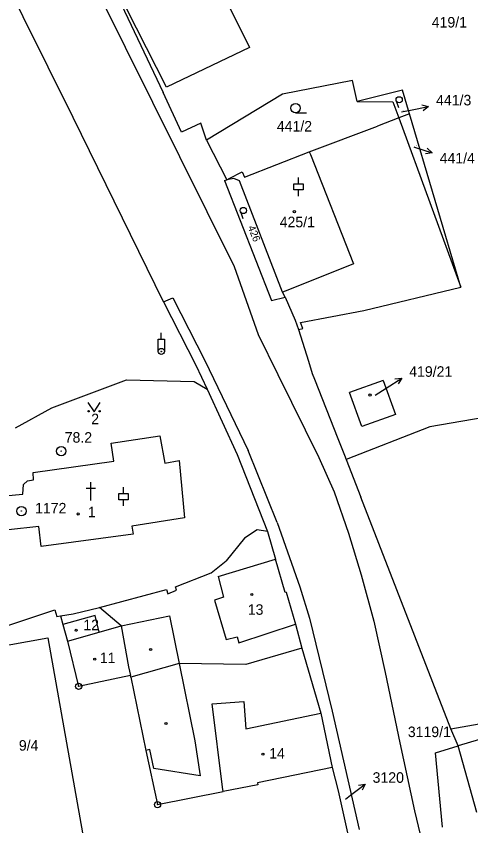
# Model space of a CAD drawing. Extents: x -736345 to -729997, y -1130177 to -1122501.
# Drawn here: x -733626.2 to -733552.8, y -1126891.5 to -1126760.8 of the extents above; entities that cross this region are included whole.
import ezdxf

# ---------------------------------------------------------------- set-up
doc = ezdxf.new("R2010")
doc.units = 0
for name, color, linetype in [('Vrstva 1', 7, 'Continuous'), ('Vrstva 16', 7, 'Continuous'), ('Vrstva 17', 7, 'Continuous'), ('Vrstva 18', 7, 'Continuous'), ('Vrstva 19', 7, 'Continuous'), ('Vrstva 25', 7, 'Continuous'), ('Vrstva 4', 7, 'Continuous')]:
    doc.layers.add(name, color=color, linetype=linetype)

msp = doc.modelspace()

# ---------------------------------------------------------------- linework, layer by layer
at = {"layer": 'Vrstva 1'}
for points in [[(-733617, -1126777.14), (-733653.37, -1126703.96)], [(-733630.68, -1126721.44), (-733590.98, -1126801.18)], [(-733600.44, -1126741.82), (-733588.52, -1126765.83)], [(-733601.94, -1126772.22), (-733616.47, -1126743.62)], [(-733616.47, -1126743.62), (-733602.44, -1126773.11)], [(-733588.52, -1126765.83), (-733601.94, -1126772.22)], [(-733571.88, -1126771.14), (-733583.17, -1126773.36)], [(-733571.13, -1126774.55), (-733571.88, -1126771.14)], [(-733599.49, -1126779.5), (-733602.44, -1126773.11)], [(-733563.83, -1126772.7), (-733571.13, -1126774.55)], [(-733562.69, -1126776.53), (-733563.83, -1126772.7)], [(-733583.17, -1126773.36), (-733595.44, -1126780.77)], [(-733571.13, -1126774.55), (-733565.34, -1126774.59)], [(-733565.34, -1126774.59), (-733564.39, -1126777.18)], [(-733562.69, -1126776.53), (-733564.39, -1126777.18)], [(-733554.36, -1126804.53), (-733562.69, -1126776.53)], [(-733602.39, -1126806.9), (-733617, -1126777.14)], [(-733596.4, -1126778.03), (-733599.49, -1126779.5)], [(-733595.44, -1126780.77), (-733596.4, -1126778.03)], [(-733564.39, -1126777.18), (-733567.85, -1126778.51)], [(-733564.39, -1126777.18), (-733554.36, -1126804.53)], [(-733578.86, -1126782.68), (-733567.85, -1126778.51)], [(-733595.44, -1126780.77), (-733592.18, -1126787.18)], [(-733589.3, -1126786.74), (-733578.86, -1126782.68)], [(-733591.79, -1126786.98), (-733589.68, -1126785.92)], [(-733589.68, -1126785.92), (-733589.3, -1126786.74)], [(-733592.56, -1126787.31), (-733592.18, -1126787.18)], [(-733592.56, -1126787.31), (-733584.96, -1126806.68)], [(-733592.18, -1126787.18), (-733591.79, -1126786.98)], [(-733591.07, -1126787), (-733592.18, -1126787.18)], [(-733590.15, -1126787.35), (-733591.07, -1126787)], [(-733583.16, -1126805.33), (-733590.15, -1126787.35)], [(-733590.98, -1126801.18), (-733587.1, -1126812.15)], [(-733570.07, -1126808.28), (-733554.36, -1126804.53)], [(-733582.75, -1126806.11), (-733583.16, -1126805.33)], [(-733602.39, -1126806.9), (-733600.91, -1126806.24)], [(-733602.39, -1126806.9), (-733597.18, -1126817.11)], [(-733600.91, -1126806.24), (-733595.71, -1126816.37)], [(-733584.96, -1126806.68), (-733582.75, -1126806.11)], [(-733582.75, -1126806.11), (-733581.16, -1126809.87)], [(-733580.27, -1126810.23), (-733570.07, -1126808.28)], [(-733581.16, -1126809.87), (-733580.58, -1126811.37)], [(-733579.89, -1126811.2), (-733580.27, -1126810.23)], [(-733587.1, -1126812.15), (-733583.93, -1126818.6)], [(-733580.58, -1126811.37), (-733579.89, -1126811.2)], [(-733580.58, -1126811.37), (-733578.99, -1126816.49)], [(-733597.18, -1126817.11), (-733595.38, -1126821.01)], [(-733595.71, -1126816.37), (-733588.71, -1126830.89)], [(-733578.99, -1126816.49), (-733578.38, -1126818.45)], [(-733583.93, -1126818.6), (-733577.33, -1126832)], [(-733578.38, -1126818.45), (-733578.01, -1126819.38)], [(-733620.45, -1126824), (-733608.4, -1126819.5)], [(-733608.4, -1126819.5), (-733597.45, -1126819.75)], [(-733597.45, -1126819.75), (-733595.38, -1126821.01)], [(-733578.01, -1126819.38), (-733574.24, -1126828.95)], [(-733566.92, -1126819.58), (-733572.34, -1126821.53)], [(-733566.92, -1126819.58), (-733564.94, -1126825.06)], [(-733595.38, -1126821.01), (-733590.52, -1126831.56)], [(-733570.36, -1126827.02), (-733572.34, -1126821.53)], [(-733626.3, -1126827.23), (-733620.45, -1126824)], [(-733564.94, -1126825.06), (-733570.36, -1126827.02)], [(-733543.7, -1126824.36), (-733559.37, -1126827.08)], [(-733559.37, -1126827.08), (-733572.91, -1126832.34)], [(-733610.88, -1126829.73), (-733603, -1126828.54)], [(-733603, -1126828.54), (-733602.19, -1126832.92)], [(-733574.24, -1126828.95), (-733573.18, -1126831.64)], [(-733610.45, -1126832.62), (-733610.88, -1126829.73)], [(-733590.52, -1126831.56), (-733585.62, -1126843.98)], [(-733584.04, -1126842.52), (-733588.71, -1126830.89)], [(-733577.33, -1126832), (-733574.86, -1126837.58)], [(-733573.18, -1126831.64), (-733572.91, -1126832.34)], [(-733623.46, -1126834.42), (-733610.45, -1126832.62)], [(-733602.19, -1126832.92), (-733599.9, -1126832.5)], [(-733599.9, -1126832.5), (-733599, -1126841.74)], [(-733572.91, -1126832.34), (-733570.52, -1126838.43)], [(-733623.39, -1126835.61), (-733623.46, -1126834.42)], [(-733625.01, -1126836.4), (-733624.35, -1126835.78)], [(-733624.35, -1126835.78), (-733623.39, -1126835.61)], [(-733625.13, -1126837.93), (-733625.01, -1126836.4)], [(-733628.04, -1126838.2), (-733625.13, -1126837.93)], [(-733574.86, -1126837.58), (-733572.51, -1126844.22)], [(-733556.01, -1126875.82), (-733570.52, -1126838.43)], [(-733599, -1126841.74), (-733607.54, -1126843.11)], [(-733622.56, -1126843.17), (-733627.45, -1126843.71)], [(-733622.18, -1126846.41), (-733622.56, -1126843.17)], [(-733607.54, -1126843.11), (-733607.33, -1126844.42)], [(-733587.3, -1126843.68), (-733589.3, -1126845.03)], [(-733585.62, -1126843.98), (-733587.3, -1126843.68)], [(-733584.04, -1126842.52), (-733580.4, -1126852.9)], [(-733607.33, -1126844.42), (-733622.18, -1126846.41)], [(-733589.3, -1126845.03), (-733592.26, -1126848.69)], [(-733585.62, -1126843.98), (-733584.34, -1126848.45)], [(-733572.51, -1126844.22), (-733570.48, -1126850.97)], [(-733594.73, -1126850.63), (-733592.26, -1126848.69)], [(-733582.75, -1126853.81), (-733584.34, -1126848.45)], [(-733600.49, -1126852.91), (-733594.73, -1126850.63)], [(-733570.48, -1126850.97), (-733568.44, -1126858.44)], [(-733600.28, -1126853.43), (-733600.49, -1126852.91)], [(-733580.4, -1126852.9), (-733578.84, -1126857.98)], [(-733612.77, -1126856.24), (-733601.91, -1126853.34)], [(-733601.91, -1126853.34), (-733601.73, -1126854.01)], [(-733601.73, -1126854.01), (-733600.28, -1126853.43)], [(-733582.62, -1126853.77), (-733582.75, -1126853.81)], [(-733582.62, -1126853.77), (-733581.09, -1126858.94)], [(-733628.92, -1126859.58), (-733619.95, -1126856.64)], [(-733619.95, -1126856.64), (-733619.64, -1126857.67)], [(-733617, -1126857.28), (-733612.77, -1126856.24)], [(-733609.24, -1126859.19), (-733612.77, -1126856.24)], [(-733619.64, -1126857.67), (-733619.05, -1126857.58)], [(-733619.05, -1126857.58), (-733617, -1126857.28)], [(-733619.05, -1126857.58), (-733618.67, -1126858.97)], [(-733578.84, -1126857.98), (-733575.14, -1126872.99)], [(-733618.67, -1126858.97), (-733617.93, -1126861.67)], [(-733612.79, -1126860.2), (-733609.24, -1126859.19)], [(-733609.24, -1126859.19), (-733608.04, -1126865.84)], [(-733581.09, -1126858.94), (-733580.05, -1126862.83)], [(-733568.44, -1126858.44), (-733566.58, -1126866.74)], [(-733617.93, -1126861.67), (-733612.79, -1126860.2)], [(-733633.7, -1126863.4), (-733621.08, -1126861.15)], [(-733621.08, -1126861.15), (-733614.62, -1126897.48)], [(-733617.93, -1126861.67), (-733616.12, -1126868.97)], [(-733580.05, -1126862.83), (-733589.13, -1126865.44)], [(-733580.05, -1126862.83), (-733577.02, -1126873.29)], [(-733608.04, -1126865.84), (-733607.76, -1126867.23)], [(-733599.86, -1126865.3), (-733607.7, -1126867.51)], [(-733589.13, -1126865.44), (-733599.86, -1126865.3)], [(-733607.76, -1126867.23), (-733616.12, -1126868.97)], [(-733607.7, -1126867.51), (-733607.76, -1126867.23)], [(-733566.58, -1126866.74), (-733564.25, -1126878.09)], [(-733607.7, -1126867.51), (-733605.24, -1126879.31)], [(-733556.01, -1126875.82), (-733534.03, -1126871.93)], [(-733577.02, -1126873.29), (-733575.14, -1126882.09)], [(-733575.14, -1126872.99), (-733570.81, -1126892.06)], [(-733554.79, -1126878.57), (-733556.01, -1126875.82)], [(-733545.93, -1126875.94), (-733554.79, -1126878.57)], [(-733564.25, -1126878.09), (-733561.87, -1126889.08)], [(-733558.47, -1126879.71), (-733554.79, -1126878.57)], [(-733605.24, -1126879.31), (-733603.37, -1126888.07)], [(-733557.34, -1126891.69), (-733558.47, -1126879.71)], [(-733575.14, -1126882.09), (-733587.22, -1126884.54)], [(-733575.14, -1126882.09), (-733574.21, -1126885.84)], [(-733587.18, -1126884.85), (-733592.77, -1126885.93)], [(-733587.22, -1126884.54), (-733587.18, -1126884.85)], [(-733603.37, -1126888.07), (-733592.77, -1126885.93)], [(-733574.21, -1126885.84), (-733572.68, -1126892.61)], [(-733561.87, -1126889.08), (-733558.82, -1126901.87)]]:
    msp.add_lwpolyline(points, dxfattribs=at)
at = {"layer": 'Vrstva 16'}
for points in [[(-733563.98, -1126776.21), (-733562.53, -1126775.93)], [(-733561.99, -1126781.85), (-733561.85, -1126781.9)], [(-733568.2, -1126821.94), (-733566.44, -1126820.81)], [(-733573.03, -1126887.17), (-733572.22, -1126886.55)]]:
    msp.add_lwpolyline(points, dxfattribs=at)
at = {"layer": 'Vrstva 25'}
for points in [[(-733564.82, -1126774.42), (-733564.465, -1126775.537)], [(-733562.53, -1126775.93), (-733559.584, -1126775.368)], [(-733560.66, -1126775.065), (-733559.584, -1126775.368), (-733560.472, -1126776.046)], [(-733581.07, -1126776.36), (-733579.32, -1126776.36)], [(-733561.85, -1126781.9), (-733559.006, -1126782.851)], [(-733559.795, -1126782.06), (-733559.006, -1126782.851), (-733560.113, -1126783.008)], [(-733580.58, -1126787.81), (-733580.58, -1126786.81)], [(-733579.83, -1126788.81), (-733581.33, -1126788.81), (-733581.33, -1126787.81), (-733579.83, -1126787.81), (-733579.83, -1126788.81)], [(-733580.58, -1126789.81), (-733580.58, -1126788.81)], [(-733589.98, -1126792.32), (-733589.575, -1126793.42)], [(-733602.77, -1126812.9), (-733602.77, -1126811.9)], [(-733603.27, -1126814.9), (-733603.27, -1126812.9), (-733602.27, -1126812.9), (-733602.27, -1126814.9)], [(-733566.44, -1126820.81), (-733563.916, -1126819.19)], [(-733565.028, -1126819.309), (-733563.916, -1126819.19), (-733564.487, -1126820.151)], [(-733614.61, -1126823.15), (-733613.61, -1126824.65), (-733612.61, -1126823.15)], [(-733614.91, -1126836.98), (-733613.41, -1126836.98)], [(-733614.16, -1126838.98), (-733614.16, -1126835.98)], [(-733608.89, -1126837.83), (-733608.89, -1126836.83)], [(-733608.14, -1126838.83), (-733609.64, -1126838.83), (-733609.64, -1126837.83), (-733608.14, -1126837.83), (-733608.14, -1126838.83)], [(-733608.89, -1126839.83), (-733608.89, -1126838.83)], [(-733572.22, -1126886.55), (-733569.831, -1126884.737)], [(-733570.93, -1126884.943), (-733569.831, -1126884.737), (-733570.325, -1126885.74)]]:
    msp.add_lwpolyline(points, dxfattribs=at)
for centre, radius in [((-733564.342, -1126774.268), 0.502), ((-733581.07, -1126775.61), 0.75), ((-733589.509, -1126792.146), 0.502), ((-733581.27, -1126792.32), 0.175), ((-733602.77, -1126814.9), 0.5), ((-733602.77, -1126814.9), 0.05), ((-733569.05, -1126821.94), 0.175), ((-733614.51, -1126824.55), 0.1), ((-733612.71, -1126824.55), 0.1), ((-733618.92, -1126831), 0.75), ((-733618.92, -1126831), 0.032), ((-733625.35, -1126840.68), 0.75), ((-733625.35, -1126840.68), 0.032), ((-733616.18, -1126841.14), 0.175), ((-733588.14, -1126854.15), 0.175), ((-733616.51, -1126859.91), 0.175), ((-733604.48, -1126863.01), 0.175), ((-733613.51, -1126864.57), 0.175), ((-733616.12, -1126868.97), 0.5), ((-733616.12, -1126868.97), 0.032), ((-733602.01, -1126874.96), 0.175), ((-733586.35, -1126879.91), 0.175), ((-733603.37, -1126888.07), 0.5), ((-733603.37, -1126888.07), 0.032)]:
    msp.add_circle(centre, radius, dxfattribs=at)
at = {"layer": 'Vrstva 4'}
for points in [[(-733578.86, -1126782.68), (-733578.69, -1126783.1)], [(-733578.69, -1126783.1), (-733571.73, -1126800.77)], [(-733571.73, -1126800.77), (-733582.33, -1126805.01)], [(-733582.33, -1126805.01), (-733583.16, -1126805.33)], [(-733593.6, -1126851.21), (-733584.34, -1126848.45)], [(-733593.6, -1126851.21), (-733592.69, -1126854.57)], [(-733592.69, -1126854.57), (-733594.18, -1126855.05)], [(-733594.18, -1126855.05), (-733592.27, -1126861.4)], [(-733613.46, -1126857.55), (-733618.67, -1126858.97)], [(-733612.79, -1126860.2), (-733613.46, -1126857.55)], [(-733609.24, -1126859.19), (-733601.43, -1126857.57)], [(-733601.43, -1126857.57), (-733599.86, -1126865.3)], [(-733590.26, -1126861.95), (-733581.09, -1126858.94)], [(-733592.27, -1126861.4), (-733590.49, -1126860.98)], [(-733590.49, -1126860.98), (-733590.26, -1126861.95)], [(-733599.86, -1126865.3), (-733597.32, -1126877.75)], [(-733594.54, -1126871.79), (-733589.45, -1126871.4)], [(-733592.86, -1126885.23), (-733594.54, -1126871.79)], [(-733589.45, -1126871.4), (-733589.1, -1126875.85)], [(-733589.1, -1126875.85), (-733577.02, -1126873.29)], [(-733597.32, -1126877.75), (-733596.5, -1126883.42)], [(-733551.8, -1126889.36), (-733554.79, -1126878.57)], [(-733604.63, -1126879.19), (-733605.24, -1126879.31)], [(-733603.99, -1126882.23), (-733604.63, -1126879.19)], [(-733596.5, -1126883.42), (-733603.99, -1126882.23)], [(-733592.77, -1126885.93), (-733592.86, -1126885.23)]]:
    msp.add_lwpolyline(points, dxfattribs=at)

# ---------------------------------------------------------------- texts
at = {"layer": 'Vrstva 16'}
for s, p in [('441/3', (-733558.38, -1126775.17)), ('441/4', (-733557.8, -1126784.55)), ('419/21', (-733562.72, -1126818.99)), ('3120', (-733568.63, -1126884.54))]:
    msp.add_text(s, height=1.7, dxfattribs=at).set_placement(p)
at = {"layer": 'Vrstva 17'}
for s, p in [('78.2', (-733618.36, -1126829.63)), ('1172', (-733623.15, -1126841.05))]:
    msp.add_text(s, height=1.7, dxfattribs=at).set_placement(p)
at = {"layer": 'Vrstva 18'}
for s, height, p in [('419/1', 1.7, (-733559.08, -1126762.6)), ('441/3', 0.1, (-733563.78, -1126776.01)), ('441/2', 1.7, (-733584.1, -1126779.39)), ('441/4', 0.1, (-733561.79, -1126781.65)), ('2', 1.7, (-733614.08, -1126826.65)), ('3119/1', 1.7, (-733562.94, -1126877.16)), ('3120', 0.1, (-733572.83, -1126886.97))]:
    msp.add_text(s, height=height, dxfattribs=at).set_placement(p)
msp.add_text('426', height=1.2, rotation=291.80232, dxfattribs=at).set_placement((-733588.811, -1126794.831))
at = {"layer": 'Vrstva 19'}
for s, height, p in [('425/1', 1.7, (-733583.64, -1126794.85)), ('419/21', 0.1, (-733568, -1126821.74)), ('1', 1.7, (-733614.62, -1126841.67)), ('13', 1.7, (-733588.79, -1126857.42)), ('12', 1.7, (-733615.35, -1126859.9)), ('11', 1.7, (-733612.69, -1126865.22)), ('9/4', 1.7, (-733625.77, -1126879.35)), ('14', 1.7, (-733585.34, -1126880.64))]:
    msp.add_text(s, height=height, dxfattribs=at).set_placement(p)

doc.saveas('drawing.dxf')
